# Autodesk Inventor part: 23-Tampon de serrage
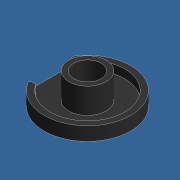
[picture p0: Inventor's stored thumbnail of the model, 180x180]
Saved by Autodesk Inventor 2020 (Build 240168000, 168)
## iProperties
Created: 2022-03
Part Number: 23-Tampon de serrage
Material: Caoutchouc
Document SubType Name: Modeling
Designer: %USERNAME%
Density: 0.93 g/cm^3
Appearance: Caoutchouc - Noir
Author: %USERNAME%
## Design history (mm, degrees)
sketch "Esquisse2"
  geometry: L1 (0, 0)-(25.5, 0); L2 (25.5, 0)-(25.5, 3); L3 (25.5, 3)-(0, 3); L4 (0, 3)-(0, 0); L5 (25.5, 3)-(22, 3); L6 (22, 3)-(22, 8); L7 (22, 8)-(25.5, 8); L8 (25.5, 8)-(25.5, 3); L9 (0, 3)-(11, 3); L10 (11, 3)-(11, 18); L11 (11, 18)-(0, 18); L12 (0, 18)-(0, 3); L13 (0, 18)-(8, 18); L14 (8, 18)-(8, 0); L15 (8, 0)-(0, 0); L16 (0, 0)-(0, 18); L17 (0, 0)-(0, -6.899); 3 further points
  constraints: 34 end point, 8 parallel, 4 horizontal, 4 perpendicular, 1 point on line, 1 vertical
  dimensions: "d0" = 51 diameter of L2 L17; "d1" = 44 diameter of L6 L17; "d2" = 3 distance between parallel lines of L1 L3; "d3" = 8 distance between parallel lines of L7 L1; "d4" = 18 distance between parallel lines of L11 L1; "d5" = 16 diameter of L14 L17; "d6" = 22 diameter of L10 L17
revolve "Révolution1" sketch "Esquisse2" stored, may be unused: angle "d7" = 90 deg
sketch "Esquisse3"
  geometry: L1 (-22.5, -21.59)-(-22.5, 27.241); C1 r 25.5 at (0, 0) reference; 3 further points
  constraints: 2 end point, 1 vertical
  dimensions: "d8" = 48 dimension on C1 L1
extrude "Extrusion1" cut sketch "Esquisse3" extent not by distance; stored distance "d9" = 0; taper "d10" = 0 deg
sketch "Esquisse4"
  geometry: L1 (-22.5, 12)-(-22.5, -12) reference; L2 (-22.5, -12)-(-18.439, -12); L3 (-18.439, -12)-(-18.439, 12); L4 (-18.439, 12)-(-22.5, 12); L5 (-22.5, 12)-(-22.5, -12); 3 further points
  constraints: 8 end point, 2 parallel, 1 horizontal, 1 perpendicular, 1 point on line, 2 other
extrude "Extrusion2" cut sketch "Esquisse4" stored distance "d11" = 10; taper "d12" = 0 deg
fillet "Congé1" dims "d13" = 1
node "Solide1"
